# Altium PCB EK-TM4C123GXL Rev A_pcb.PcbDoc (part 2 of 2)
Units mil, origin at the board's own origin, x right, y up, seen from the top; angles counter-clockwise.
Board outline 2000 x 2600 mil, 2 copper layers (Top, Bottom), stack 12.7 mil thick; 107 components, 90 nets, 409 pads, 197 vias.
Unrouted connection lines stored in the file: 66.
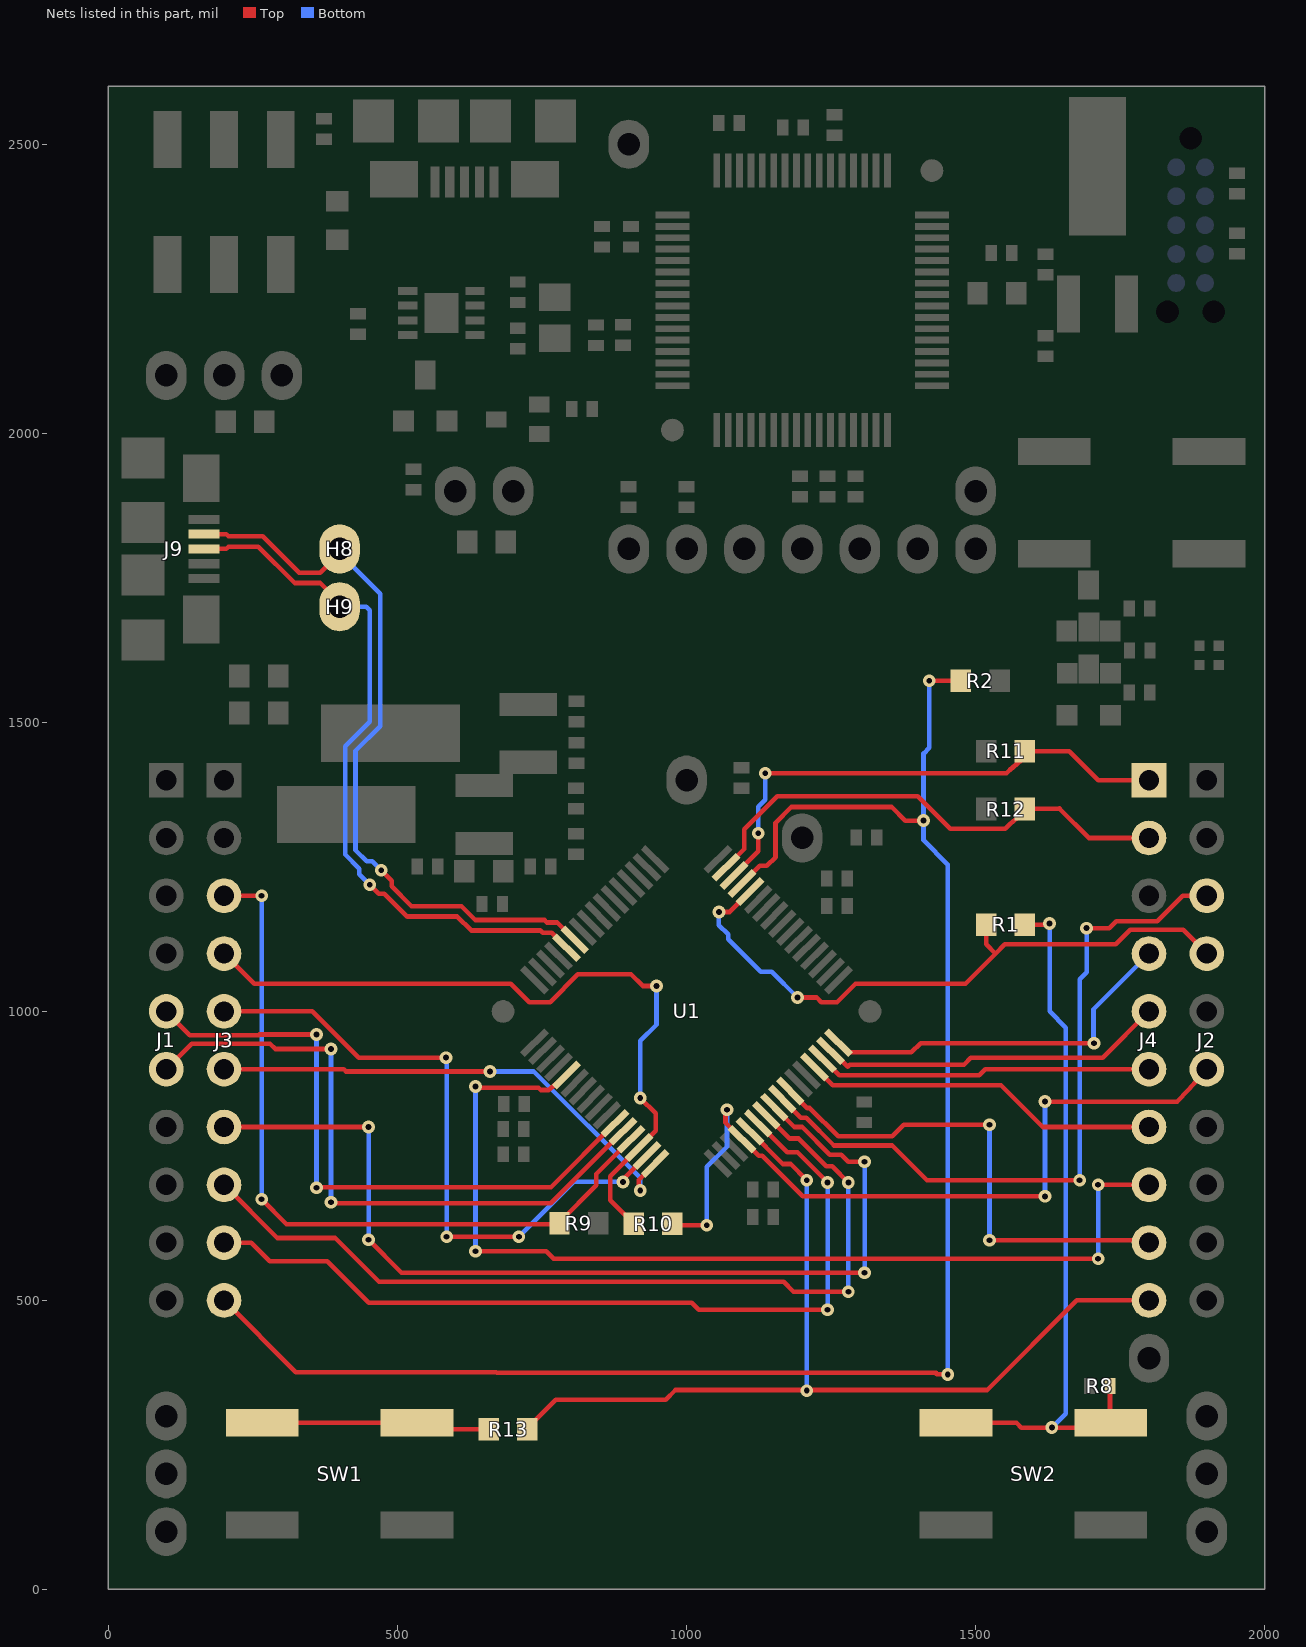
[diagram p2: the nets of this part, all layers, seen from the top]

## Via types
v1: diameter 22, hole 10, Top to Bottom, 197 vias

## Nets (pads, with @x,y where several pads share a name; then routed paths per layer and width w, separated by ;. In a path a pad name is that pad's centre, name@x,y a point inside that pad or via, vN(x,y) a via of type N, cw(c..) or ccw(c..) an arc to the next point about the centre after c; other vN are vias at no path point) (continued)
PB7: J2.6 R10.2 U1.4 | length 1376
  Top w8: R10.2@975.48,632.6 975.48,630 v1(1035,630) ; v1(1070,830) 1067.39,830 1067.39,807.34 U1.4@1096.04,778.68 1124.7,750.02 1131.1,750.02 1201.12,680 v1(1620,680) ; v1(1620,844) 1849,844 1868,864 J2.6@1900,900
  Bottom w8: v1(1035,630) 1035,731 1070,766 v1(1070,830) ; v1(1620,680) v1(1620,844)
PC4: J4.4 U1.16 | length 652.6
  Top w8: U1.16@1263.08,945.71 1279.78,929.01 1389.01,929.01 1405,945 v1(1705,945)
  Bottom w8: v1(1705,945) 1704,944 1704,1004 J4.4@1800,1100
PC5: J4.5 U1.15 | length 602.8
  Top w8: U1.15@1249.16,931.79 1250.51,933.14 1279.16,904.48 1282.68,908 1480,908 1492,920 1720,920 J4.5@1800,1000
PC6: J4.6 U1.14 | length 581.1
  Top w8: U1.14@1235.24,917.88 1263.9,889.22 1506.06,889.22 1516.84,900 J4.6@1800,900
PC7: J4.7 U1.13 | length 621.7
  Top w8: U1.13@1221.32,903.96 1253.27,872 1544,872 1616,800 J4.7@1800,800
PD0: J3.3 R9.1 U1.61 | length 1320.2
  Top w8: J3.3@200,1200 v1(265,1200) ; v1(265,675) 308,632 778.93,632 R9.1@780.27,633.34 780.27,635.31 844,699.04 844,718.73 U1.61@903.96,778.68
  Bottom w8: v1(265,675) v1(265,1200)
PD1: J3.4 R10.1 U1.62 | length 1294.9
  Top w8: J3.4@200,1100 252,1048 695.97,1048 727.97,1016 764,1016 812,1064 904,1064 924,1044 v1(948,1044) ; R10.1@908.55,632.6 907.49,632.6 907.49,633.51 868,673 868,714.89 U1.62@917.88,764.76 946.53,793.42 946.53,823.47 v1(920,850)
  Bottom w8: v1(920,850) 920,949.16 948,977.16 v1(948,1044)
PD2: J3.5 U1.63 | length 1140.5
  Top w8: J3.5@200,1000 352.89,1000 432.89,920 v1(584,920) ; v1(585,610) v1(710,610) ; v1(890,705) 891,705 892,704 892,711.05 U1.63@931.79,750.84
  Bottom w8: v1(584,920) 585,919 v1(585,610) ; v1@708,608 v1(710,610) 805,705 v1(890,705)
PD3: J3.6 U1.64 | length 883.9
  Top w8: J3.6@200,900 406.94,900 410.94,896 v1(660,896) ; v1(920,690) 920,688 917.06,690.94 917.06,708.27 U1.64@945.71,736.92
  Bottom w8: v1(660,896) 736,896 920,712 v1(920,690)
PD6: J4.8 U1.53 | length 1753.5
  Top w8: v1(635,585) 757,585 770,572 v1(1712,572) ; v1(635,870) 635,869 636,868 744,868 748,864 761.32,864 785.77,883.21 U1.53@792.6,890.04 ; v1(1712,700) J4.8@1800,700
  Bottom w8: v1(635,585) v1(635,870) ; v1(1712,572) v1(1712,700)
PD7: J4.9 U1.10 | length 865.1
  Top w8: U1.10@1179.56,862.2 1208.99,832.76 1213.48,832.76 1262.24,784 1356,784 1376,804 v1(1524,804) ; v1(1524,604) 1800,604 J4.9@1800,600
  Bottom w8: v1(1524,604) v1(1524,804)
PE0: J2.3 U1.9 | length 1244.6
  Top w8: U1.9@1165.64,848.28 1197.92,816 1207.05,816 1255.05,768 1356,768 1416,708 v1(1680,708) ; v1(1692,1144) 1731.55,1144 1743.55,1156 1814.49,1156 1858.49,1200 J2.3@1900,1200
  Bottom w8: v1(1680,708) 1680,1055.61 1692,1067.61 v1(1692,1144)
PE1: J3.7 U1.8 | length 1716.8
  Top w8: J3.7@200,800 v1(450,800) ; v1(450,605) 507,548 v1(1308,548) ; U1.8@1151.72,834.36 1186.08,800 1199.86,800 1247.86,752 1267.61,752 1279.61,740 v1(1308,740)
  Bottom w8: v1(450,605) 450,798 452,800 v1(450,800) ; v1(1308,548) v1(1308,740)
PE2: J3.8 U1.7 | length 1536.1
  Top w8: J3.8@200,700 292,608 392,608 468,532 1168,532 1185,515 v1(1280,515) ; U1.7@1137.8,820.44 1178.24,780 1193.93,780 1241.93,732 1252,732 v1(1280,704)
  Bottom w8: v1(1280,515) v1(1280,704)
PE3: J3.9 U1.6 | length 1474.6
  Top w8: J3.9@200,600 246.93,600 278.93,568 378.5,568 450.5,496 1008.88,496 1020.88,484 v1(1244,484) ; U1.6@1123.88,806.52 1174.4,756 1192,756 v1(1244,704)
  Bottom w8: v1(1244,484) v1(1244,704)
PE4: J1.5 U1.59 | length 1105.3
  Top w8: J1.5@100,1000 141,959 260,959 261,960 v1(360,960) ; v1(360,695) 360,696 765.6,696 U1.59@876.12,806.52
  Bottom w8: v1(360,695) v1(360,960)
PE5: J1.6 U1.60 | length 1132
  Top w8: J1.6@100,900 144,944 279.43,944 288.43,935 v1(385,935) ; v1(385,670) 384,669 384,668 765.44,668 U1.60@890.04,792.6
  Bottom w8: v1(385,670) v1(385,935)
PF0: J2.4 R1.1 U1.28 | length 1120.9
  Top w8: v1(1056,1172) 1074.56,1172 U1.28@1109.96,1207.4 ; v1(1192,1024) 1225.02,1024 1233.02,1016 1260.36,1016 1292.36,1048 1482.57,1048 1534.52,1099.96 ; R1.1@1518.54,1150 1518.54,1115.95 1534.52,1099.96 ; J2.4@1900,1100 1859,1141 1767.32,1141 1742.32,1116 1550.57,1116 1534.52,1099.96
  Bottom w8: v1(1056,1172) 1056,1149.14 1072,1133.14 1072,1124.89 1128.11,1068.78 1147.22,1068.78 v1(1192,1024)
PF1: J3.10 R2.1 U1.29 | length 2995.4
  Top w8: J3.10@200,500 324,376 671,376 672,375 1432,375 1433,372 v1(1452,372) ; U1.29@1096.04,1221.32 1126.71,1251.99 1139.1,1251.99 1154,1266.89 1154,1326.55 1180.95,1353.5 1354.73,1353.5 1378.23,1330 v1(1410,1330) ; v1(1420,1572) R2.1@1474.54,1572
  Bottom w8: v1(1420,1572) 1420,1456 1410,1446 v1(1410,1330) 1410,1296 1452,1254 v1(1452,372)
PF2: J4.1 R11.1 U1.30 | length 904.4
  Top w8: U1.30@1082.12,1235.24 1124,1277.11 v1(1124,1308) ; v1(1136,1412) 1553.46,1412 1558.99,1417.52 1585.46,1439.92 R11.1@1585.46,1450 1662,1450 1712,1400 J4.1@1800,1400
  Bottom w8: v1(1124,1308) 1124,1354 1136,1366 v1(1136,1412)
PF3: J4.2 R12.1 U1.31 | length 862.4
  Top w8: U1.31@1068.21,1249.16 1100,1280.95 1100,1315.11 1156.89,1372 1400,1372 1456,1316 1551.46,1316 1558.99,1323.52 1585.46,1345.92 R12.1@1585.46,1350 1645.14,1350.86 1696,1300 J4.2@1800,1300
PF4: J4.10 R13.1 U1.5 | length 1667.2
  Top w8: R13.1@724.75,277.06 724.75,279.02 773.73,328 964,328 981,345 v1@1207,345 ; U1.5@1109.96,792.6 1166.56,736 1180,736 v1(1208,708) ; v1(1208,344) v1@1207,345 ; J4.10@1800,500 1675,500 1520,345 v1@1207,345
  Bottom w8: v1(1208,344) v1(1208,708)
USB_DM: H8.1 J9.2 U1.43 | length 1300.5
  Top w8: J9.2@165.32,1825.59 204,1825.59 207.8,1821.8 266.93,1821.8 329.73,1759 366.5,1759 400,1792.5 H8.1@400,1800 ; v1(472,1244) 490.06,1225.94 490.06,1216.17 524.19,1182.04 610.79,1182.04 634.83,1158 754.23,1158 758.49,1153.74 776.66,1153.74 U1.43@806.52,1123.88
  Bottom w8: H8.1@400,1800 400,1792.5 469.99,1722.51 469.99,1493.49 427.39,1450.88 427.39,1278.84 446.67,1259.56 456.44,1259.56 v1(472,1244)
USB_DP: H9.1 J9.3 U1.44 | length 1234.2
  Top w8: J9.3@165.32,1800 204,1800 207.8,1803.8 259.48,1803.8 322.27,1741 366.5,1741 400,1707.5 H9.1@400,1700 ; v1(452,1219) 467.56,1203.44 477.33,1203.44 516.73,1164.04 603.34,1164.04 627.38,1140 746.86,1140 751.12,1135.74 766.82,1135.74 U1.44@792.6,1109.96
  Bottom w8: H9.1@400,1700 446,1700 451.99,1694.01 451.99,1500.94 409.39,1458.34 409.39,1271.38 433.94,1246.83 433.94,1237.06 v1(452,1219)
USR_SW1: R13.2 SW1.1 SW1.3 | length 403.2
  Top w8: SW1.1@266.14,288.58 SW1.3@533.86,288.58 533.86,277.06 R13.2@657.82,277.06
USR_SW2: R1.2 R8.2 SW2.1 SW2.3 | length 1300.2
  Top w8: SW2.1@1466.14,288.58 1570.78,288.58 1579.36,280 v1(1632,280) SW2.3@1732.51,280 ; R1.2@1585.46,1150 1626,1150 v1(1628,1152) ; R8.2@1732.51,352.28 SW2.3@1732.51,280 ; SW2.3@1732.51,280 SW2.3@1732.68,280 ; SW2.3@1732.51,280 1732.51,278.74 SW2.3@1732.68,280 ; SW2.3@1732.68,280 1733.86,280 SW2.3@1733.86,288.58 SW2.3@1732.68,280
  Bottom w8: v1(1628,1152) 1628,1000 1656,972 1656,304 v1(1632,280)
pads on no net: J5.1 J5.7 J5.11 J5.12 J5.13 J9.10 J9.11 J11.4 J11.10 J11.11 Q1.1 Q1.2 Q1.3 Q2.1 Q2.2 Q2.3 Q3.1 Q3.2 Q3.3 U1.65 U1.66 U2.1 U2.4 U2.5 U2.6 U2.7 U2.8 U2.9 U2.10 U2.13 U2.14 U2.15 U2.16 U2.28 U2.31 U2.33 U2.36 U2.47 U2.48 U2.57 U2.58 U2.59 U2.60 U2.61 U2.62 U2.63 U2.65 U2.66 U8.2 U8.6 U8.7 U8.10 U8.11 U8.12 U8.13 Y1.3 Y2.3 Y5.3
copper on no net: | length 550.8
  Bottom w4: 1734.32,1998.88 1734.5,1998.88 ; 1734.32,1999.6 1734.5,1999.6 ; 1734.32,2001.04 1736.66,2001.04 ; 1734.32,2001.76 1735.22,2001.76 ; 1735.04,2003.2 1735.22,2003.2 ; 1735.04,2003.92 1735.94,2003.92 ; 1735.76,2000.32 1735.94,2000.32 ; 1735.76,2002.48 1736.66,2002.48 ; 1735.76,2004.64 1737.38,2004.64 ; 1736.48,2001.76 1736.66,2001.76 ; 1736.48,2003.2 1738.1,2003.2 ; 1737.2,2005.36 1739.54,2005.36 ; 1737.92,2002.48 1738.1,2002.48 ; 1738.64,2003.92 1738.82,2003.92 ; 1738.64,2004.64 1738.82,2004.64 ; 1738.64,2006.08 1741.7,2006.08 ; 1739.36,2006.8 1742.42,2006.8 ; 1740.8,2007.52 1740.98,2007.52 ; 1740.8,2008.24 1743.86,2008.24 ; 1741.52,2008.96 1741.7,2008.96 ; 1741.52,2009.68 1742.42,2009.68 ; 1742.24,2007.52 1743.14,2007.52 ; 1742.24,2010.4 1743.14,2010.4 ; 1742.96,2011.12 1743.14,2011.12 ; 1742.96,2011.84 1744.58,2011.84 ; 1743.68,2008.96 1744.58,2008.96 ; 1743.68,2009.68 1745.3,2009.68 ; 1743.68,2012.56 1744.58,2012.56 ; 1744.4,1993.84 1745.3,1993.84 ; 1744.4,1994.56 1744.58,1994.56 ; 1744.4,1995.28 1745.3,1995.28 ; 1744.4,1996 1745.3,1996 ; 1744.4,1996.72 1745.3,1996.72 ; 1744.4,1997.44 1744.58,1997.44 ; 1744.4,1998.16 1745.3,1998.16 ; 1744.4,2010.4 1746.02,2010.4 ; 1744.4,2013.28 1746.02,2013.28 ; 1745.12,1991.68 1745.3,1991.68 ; 1745.12,1992.4 1745.3,1992.4 ; 1745.12,1993.12 1746.74,1993.12 ; 1745.12,1998.88 1745.3,1998.88 ; 1745.12,1999.6 1749.62,1999.6 ; 1745.12,2000.32 1746.74,2000.32 ; 1745.12,2001.04 1746.74,2001.04 ; 1745.12,2002.48 1746.74,2002.48 ; 1745.12,2011.12 1745.3,2011.12 ; 1745.84,1987.36 1746.74,1987.36 ; 1745.84,1988.08 1746.02,1988.08 ; 1745.84,1988.8 1746.02,1988.8 ; 1745.84,1989.52 1746.02,1989.52 ; 1745.84,1990.24 1746.02,1990.24 ; 1745.84,1990.96 1746.02,1990.96 ; 1745.84,2001.76 1746.74,2001.76 ; 1745.84,2003.92 1746.02,2003.92 ; 1745.84,2011.84 1746.02,2011.84 ; 1745.84,2014 1746.02,2014 ; 1745.84,2014.72 1746.74,2014.72 ; 1746.56,1985.92 1748.18,1985.92 ; 1746.56,1986.64 1746.74,1986.64 ; 1746.56,1993.84 1748.18,1993.84 ; 1746.56,2003.2 1747.46,2003.2 ; 1746.56,2004.64 1748.18,2004.64 ; 1746.56,2011.12 1746.74,2011.12 ; 1746.56,2015.44 1746.74,2015.44 ; 1746.56,2016.16 1748.18,2016.16 ; 1747.28,1983.04 1748.18,1983.04 ; 1747.28,1983.76 1747.46,1983.76 ; 1747.28,1984.48 1747.46,1984.48 ; 1747.28,1985.2 1748.9,1985.2 ; 1747.28,1998.88 1748.18,1998.88 ; 1747.28,2003.92 1748.18,2003.92 ; 1747.28,2005.36 1748.9,2005.36 ; 1747.28,2011.84 1747.46,2011.84 ; 1747.28,2012.56 1748.18,2012.56 ; 1747.28,2014 1747.46,2014 ; 1747.28,2016.88 1748.9,2016.88 ; 1748,1980.88 1748.9,1980.88 ; 1748,1981.6 1748.9,1981.6 ; 1748,1982.32 1748.18,1982.32 ; 1748,1986.64 1748.18,1986.64 ; 1748,1987.36 1748.18,1987.36 ; 1748,1988.08 1748.18,1988.08 ; 1748,1988.8 1748.18,1988.8 ; 1748,1989.52 1748.18,1989.52 ; 1748,1990.24 1748.18,1990.24 ; 1748,1990.96 1748.18,1990.96 ; 1748,1991.68 1748.18,1991.68 ; 1748,1992.4 1748.18,1992.4 ; 1748,1993.12 1748.18,1993.12 ; 1748,1994.56 1748.18,1994.56 ; 1748,1995.28 1748.18,1995.28 ; 1748,1996 1748.18,1996 ; 1748,1996.72 1748.18,1996.72 ; 1748,1997.44 1748.18,1997.44 ; 1748,1998.16 1748.18,1998.16 ; 1748,2000.32 1751.06,2000.32 ; 1748,2013.28 1748.9,2013.28 ; 1748.72,1980.16 1749.62,1980.16 ; 1748.72,1984.48 1749.62,1984.48 ; 1748.72,2006.08 1748.9,2006.08 ; 1748.72,2006.8 1749.62,2006.8 ; 1748.72,2014 1749.62,2014 ; 1748.72,2017.6 1751.06,2017.6 ; 1749.44,1979.44 1749.62,1979.44 ; 1749.44,1983.76 1750.34,1983.76 ; 1749.44,2001.04 1753.22,2001.04 ; 1749.44,2007.52 1749.62,2007.52 ; 1749.44,2014.72 1750.34,2014.72 ; 1749.44,2018.32 1749.62,2018.32 ; 1750.16,1978.72 1750.34,1978.72 ; 1750.16,2008.24 1750.34,2008.24 ; 1750.16,2008.96 1752.5,2008.96 ; 1750.88,1978 1751.06,1978 ; 1750.88,1983.04 1751.78,1983.04 ; 1750.88,2015.44 1752.5,2015.44 ; 1750.88,2018.32 1753.22,2018.32 ; 1751.6,1976.56 1752.5,1976.56 ; 1751.6,1977.28 1751.78,1977.28 ; 1751.6,1980.16 1752.5,1980.16 ; 1751.6,1980.88 1751.78,1980.88 ; 1751.6,1981.6 1751.78,1981.6 ; 1751.6,1982.32 1751.78,1982.32 ; 1751.6,2006.08 1753.22,2006.08 ; 1751.6,2006.8 1752.5,2006.8 ; 1751.6,2007.52 1752.5,2007.52 ; 1751.6,2008.24 1752.5,2008.24 ; 1752.32,1975.84 1753.22,1975.84 ; 1752.32,1978.72 1753.22,1978.72 ; 1752.32,1979.44 1752.5,1979.44 ; 1752.32,2001.76 1753.22,2001.76 ; 1752.32,2003.92 1753.22,2003.92 ; 1752.32,2004.64 1753.22,2004.64 ; 1752.32,2005.36 1753.22,2005.36 ; 1752.32,2009.68 1752.5,2009.68 ; 1752.32,2010.4 1752.5,2010.4 ; 1752.32,2011.12 1752.5,2011.12 ; 1752.32,2011.84 1752.5,2011.84 ; 1752.32,2012.56 1752.5,2012.56 ; 1752.32,2013.28 1752.5,2013.28 ; 1752.32,2014 1752.5,2014 ; 1752.32,2014.72 1752.5,2014.72 ; 1752.32,2016.16 1752.5,2016.16 ; 1752.32,2016.88 1752.5,2016.88 ; 1752.32,2017.6 1753.22,2017.6 ; 1752.32,2019.04 1753.94,2019.04 ; 1753.04,1975.12 1754.66,1975.12 ; 1753.04,1978 1754.66,1978 ; 1753.04,1997.44 1753.94,1997.44 ; 1753.04,1998.16 1753.94,1998.16 ; 1753.04,1998.88 1753.94,1998.88 ; 1753.04,1999.6 1753.94,1999.6 ; 1753.04,2000.32 1753.22,2000.32 ; 1753.04,2002.48 1753.22,2002.48 ; 1753.04,2003.2 1753.22,2003.2 ; 1753.04,2029.12 1753.22,2029.12 ; 1753.04,2029.84 1753.22,2029.84 ; 1753.04,2030.56 1753.22,2030.56 ; 1753.04,2031.28 1753.22,2031.28 ; 1753.76,1977.28 1754.66,1977.28 ; 1753.76,1996 1754.66,1996 ; 1753.76,1996.72 1753.94,1996.72 ; 1753.76,2019.76 1756.1,2019.76 ; 1753.76,2025.52 1756.1,2025.52 ; 1753.76,2026.24 1753.94,2026.24 ; 1753.76,2026.96 1753.94,2026.96 ; 1753.76,2027.68 1753.94,2027.68 ; 1753.76,2028.4 1753.94,2028.4 ; 1753.76,2032 1753.94,2032 ; 1753.76,2032.72 1753.94,2032.72 ; 1753.76,2033.44 1754.66,2033.44 ; 1754.48,1973.68 1754.66,1973.68 ; 1754.48,1974.4 1754.66,1974.4 ; 1754.48,1975.84 1754.66,1975.84 ; 1754.48,1976.56 1754.66,1976.56 ; 1754.48,1993.84 1754.66,1993.84 ; 1754.48,1994.56 1754.66,1994.56 ; 1754.48,1995.28 1754.66,1995.28 ; 1754.48,2024.08 1756.1,2024.08 ; 1754.48,2024.8 1754.66,2024.8 ; 1754.48,2029.12 1755.38,2029.12 ; 1754.48,2029.84 1755.38,2029.84 ; 1754.48,2034.16 1755.38,2034.16 ; 1755.2,1967.92 1755.38,1967.92 ; 1755.2,1968.64 1755.38,1968.64 ; 1755.2,1969.36 1757.54,1969.36 ; 1755.2,1970.08 1756.82,1970.08 ; 1755.2,1970.8 1756.1,1970.8 ; 1755.2,1972.24 1756.82,1972.24 ; 1755.2,1972.96 1756.1,1972.96 ; 1755.2,1991.68 1756.1,1991.68 ; 1755.2,1992.4 1755.38,1992.4 ; 1755.2,1993.12 1755.38,1993.12 ; 1755.2,2022.64 1756.82,2022.64 ; 1755.2,2023.36 1756.1,2023.36 ; 1755.2,2026.24 1755.38,2026.24 ; 1755.2,2026.96 1756.1,2026.96 ; 1755.2,2027.68 1755.38,2027.68 ; 1755.2,2028.4 1755.38,2028.4 ; 1755.2,2034.88 1756.1,2034.88 ; 1755.92,1966.48 1756.82,1966.48 ; 1755.92,1967.2 1756.82,1967.2 ; 1755.92,1971.52 1756.1,1971.52 ; 1755.92,1990.24 1756.82,1990.24 ; 1755.92,1990.96 1756.1,1990.96 ; 1755.92,2020.48 1757.54,2020.48 ; 1755.92,2021.92 1763.3,2021.92 ; 1755.92,2024.8 1756.1,2024.8 ; 1755.92,2030.56 1756.82,2030.56 ; 1755.92,2035.6 1756.1,2035.6 ; 1756.64,1964.32 1758.26,1964.32 ; 1756.64,1965.76 1757.54,1965.76 ; 1756.64,1989.52 1757.54,1989.52 ; 1756.64,2021.2 1758.26,2021.2 ; 1756.64,2031.28 1756.82,2031.28 ; 1756.64,2032 1757.54,2032 ; 1756.64,2036.32 1758.26,2036.32 ; 1757.36,1963.6 1761.86,1963.6 ; 1757.36,1965.04 1757.54,1965.04 ; 1757.36,1968.64 1758.26,1968.64 ; 1757.36,1988.8 1758.26,1988.8 ; 1757.36,2032.72 1757.54,2032.72 ; 1757.36,2033.44 1758.26,2033.44 ; 1757.36,2039.92 1758.26,2039.92 ; 1757.36,2040.64 1758.26,2040.64 ; 1757.36,2041.36 1758.26,2041.36 ; 1757.36,2042.08 1758.98,2042.08 ; 1757.36,2042.8 1759.7,2042.8 ; 1757.36,2043.52 1757.54,2043.52 ; 1757.36,2044.24 1758.26,2044.24 ; 1757.36,2044.96 1758.26,2044.96 ; 1758.08,1962.88 1758.98,1962.88 ; 1758.08,1987.36 1758.98,1987.36 ; 1758.08,1988.08 1758.26,1988.08 ; 1758.08,2034.16 1758.98,2034.16 ; 1758.08,2034.88 1759.7,2034.88 ; 1758.08,2035.6 1758.26,2035.6 ; 1758.08,2037.04 1758.26,2037.04 ; 1758.08,2037.76 1758.26,2037.76 ; 1758.08,2038.48 1758.98,2038.48 ; 1758.08,2039.2 1758.98,2039.2 ; 1758.08,2045.68 1758.98,2045.68 ; 1758.8,1985.92 1759.7,1985.92 ; 1758.8,1986.64 1758.98,1986.64 ; 1758.8,2022.64 1760.42,2022.64 ; 1758.8,2043.52 1758.98,2043.52 ; 1758.8,2046.4 1760.42,2046.4 ; 1759.52,1961.44 1764.02,1961.44 ; 1759.52,1962.16 1760.42,1962.16 ; 1759.52,1984.48 1760.42,1984.48 ; 1759.52,1985.2 1759.7,1985.2 ; 1759.52,2035.6 1761.14,2035.6 ; 1759.52,2044.24 1759.7,2044.24 ; 1760.24,1983.76 1761.86,1983.76 ; 1760.24,2044.96 1760.42,2044.96 ; 1760.24,2047.12 1760.42,2047.12 ; 1761.68,1964.32 1762.58,1964.32 ; 1761.68,1982.32 1761.86,1982.32 ; 1761.68,1983.04 1762.58,1983.04 ; 1761.68,2021.2 1763.3,2021.2 ; 1761.68,2036.32 1766.18,2036.32 ; 1762.4,1981.6 1764.02,1981.6 ; 1762.4,2037.04 1763.3,2037.04 ; 1762.4,2037.76 1764.02,2037.76 ; 1763.12,1962.16 1764.74,1962.16 ; 1763.12,1962.88 1764.02,1962.88 ; 1763.12,1963.6 1763.3,1963.6 ; 1763.12,1980.88 1764.74,1980.88 ; 1763.12,1982.32 1763.3,1982.32 ; 1763.84,2020.48 1769.78,2020.48 ; 1763.84,2038.48 1764.02,2038.48 ; 1763.84,2039.2 1764.74,2039.2 ; 1763.84,2039.92 1764.74,2039.92 ; 1763.84,2040.64 1764.74,2040.64 ; 1763.84,2041.36 1765.46,2041.36 ; 1763.84,2042.08 1765.46,2042.08 ; 1764.56,1980.16 1765.46,1980.16 ; 1764.56,2021.2 1765.46,2021.2 ; 1764.56,2042.8 1773.38,2042.8 ; 1765.28,1979.44 1766.9,1979.44 ; 1766,2019.76 1768.34,2019.76 ; 1766,2037.04 1771.22,2037.04 ; 1766,2043.52 1772.66,2043.52 ; 1766.72,1978.72 1769.78,1978.72 ; 1767.44,2019.04 1768.34,2019.04 ; 1768.16,1978 1769.06,1978 ; 1768.16,1979.44 1769.78,1979.44 ; 1768.16,2018.32 1769.06,2018.32 ; 1768.88,1980.16 1770.5,1980.16 ; 1768.88,2017.6 1770.5,2017.6 ; 1769.6,2014.72 1770.5,2014.72 ; 1769.6,2015.44 1770.5,2015.44 ; 1769.6,2016.16 1770.5,2016.16 ; 1769.6,2016.88 1770.5,2016.88 ; 1769.6,2042.08 1774.1,2042.08 ; 1770.32,1980.88 1771.94,1980.88 ; 1770.32,1993.84 1771.22,1993.84 ; 1770.32,1994.56 1771.22,1994.56 ; 1770.32,1995.28 1771.22,1995.28 ; 1770.32,1996 1771.22,1996 ; 1770.32,1996.72 1770.5,1996.72 ; 1770.32,1997.44 1770.5,1997.44 ; 1770.32,1998.16 1770.5,1998.16 ; 1770.32,1998.88 1770.5,1998.88 ; 1770.32,1999.6 1770.5,1999.6 ; 1770.32,2000.32 1770.5,2000.32 ; 1770.32,2001.04 1770.5,2001.04 ; 1770.32,2001.76 1770.5,2001.76 ; 1770.32,2002.48 1770.5,2002.48 ; 1770.32,2003.2 1770.5,2003.2 ; 1770.32,2003.92 1770.5,2003.92 ; 1770.32,2004.64 1770.5,2004.64 ; 1770.32,2005.36 1770.5,2005.36 ; 1770.32,2006.08 1770.5,2006.08 ; 1770.32,2006.8 1770.5,2006.8 ; 1770.32,2007.52 1771.22,2007.52 ; 1770.32,2008.24 1771.22,2008.24 ; 1770.32,2008.96 1771.22,2008.96 ; 1770.32,2009.68 1770.5,2009.68 ; 1770.32,2010.4 1770.5,2010.4 ; 1770.32,2011.12 1770.5,2011.12 ; 1770.32,2011.84 1770.5,2011.84 ; 1770.32,2012.56 1770.5,2012.56 ; 1770.32,2013.28 1770.5,2013.28 ; 1770.32,2014 1770.5,2014 ; 1771.04,1981.6 1771.94,1981.6 ; 1771.04,1990.24 1771.94,1990.24 ; 1771.04,1990.96 1771.94,1990.96 ; 1771.04,1993.12 1771.94,1993.12 ; 1771.04,2018.32 1771.22,2018.32 ; 1771.04,2019.04 1771.94,2019.04 ; 1771.04,2019.76 1774.82,2019.76 ; 1771.04,2020.48 1772.66,2020.48 ; 1771.04,2036.32 1777.7,2036.32 ; 1771.76,1979.44 1772.66,1979.44 ; 1771.76,1980.16 1771.94,1980.16 ; 1771.76,1982.32 1771.94,1982.32 ; 1771.76,1983.04 1772.66,1983.04 ; 1771.76,1983.76 1772.66,1983.76 ; 1771.76,1988.08 1772.66,1988.08 ; 1771.76,1988.8 1771.94,1988.8 ; 1771.76,1989.52 1771.94,1989.52 ; 1771.76,1991.68 1771.94,1991.68 ; 1771.76,1992.4 1771.94,1992.4 ; 1772.48,1978.72 1777.7,1978.72 ; 1772.48,1984.48 1772.66,1984.48 ; 1772.48,1985.2 1772.66,1985.2 ; 1772.48,1985.92 1772.66,1985.92 ; 1772.48,1986.64 1772.66,1986.64 ; 1772.48,1987.36 1772.66,1987.36 ; 1773.2,2039.2 1774.1,2039.2 ; 1773.2,2040.64 1774.1,2040.64 ; 1773.2,2041.36 1774.1,2041.36 ; 1773.92,2037.76 1775.54,2037.76 ; 1773.92,2038.48 1774.82,2038.48 ; 1773.92,2039.92 1774.1,2039.92 ; 1774.64,1978 1776.26,1978 ; 1774.64,2020.48 1775.54,2020.48 ; 1774.64,2037.04 1774.82,2037.04 ; 1775.36,2021.2 1777.7,2021.2 ; 1776.8,2035.6 1779.86,2035.6 ; 1777.52,1979.44 1778.42,1979.44 ; 1777.52,2021.92 1779.86,2021.92 ; 1778.24,1980.16 1779.14,1980.16 ; 1778.96,1962.16 1779.86,1962.16 ; 1778.96,1962.88 1782.74,1962.88 ; 1778.96,1963.6 1779.14,1963.6 ; 1778.96,1964.32 1779.14,1964.32 ; 1778.96,1965.04 1779.14,1965.04 ; 1778.96,1980.88 1779.86,1980.88 ; 1779.68,1961.44 1780.58,1961.44 ; 1779.68,1965.76 1780.58,1965.76 ; 1779.68,1966.48 1782.02,1966.48 ; 1779.68,1981.6 1781.3,1981.6 ; 1779.68,2034.88 1782.02,2034.88 ; 1780.4,1960.72 1784.18,1960.72 ; 1780.4,1982.32 1782.02,1982.32 ; 1780.4,2022.64 1782.74,2022.64 ; 1780.4,2034.16 1781.3,2034.16 ; 1780.4,2043.52 1780.58,2043.52 ; 1780.4,2044.96 1781.3,2044.96 ; 1780.4,2047.84 1780.58,2047.84 ; 1781.12,1967.2 1782.74,1967.2 ; 1781.12,1969.36 1783.46,1969.36 ; 1781.12,1970.08 1782.02,1970.08 ; 1781.12,1983.04 1783.46,1983.04 ; 1781.12,2033.44 1782.74,2033.44 ; 1781.12,2044.24 1782.02,2044.24 ; 1781.12,2045.68 1782.02,2045.68 ; 1781.12,2046.4 1781.3,2046.4 ; 1781.12,2047.12 1781.3,2047.12 ; 1781.84,1963.6 1782.74,1963.6 ; 1781.84,1964.32 1782.74,1964.32 ; 1781.84,1965.04 1782.74,1965.04 ; 1781.84,1965.76 1782.02,1965.76 ; 1781.84,1967.92 1782.74,1967.92 ; 1781.84,1968.64 1782.74,1968.64 ; 1781.84,1970.8 1784.18,1970.8 ; 1781.84,1971.52 1782.02,1971.52 ; 1781.84,1972.24 1782.74,1972.24 ; 1781.84,1972.96 1782.74,1972.96 ; 1781.84,1983.76 1782.74,1983.76 ; 1781.84,2032.72 1782.74,2032.72 ; 1781.84,2035.6 1782.02,2035.6 ; 1781.84,2036.32 1783.46,2036.32 ; 1781.84,2042.8 1782.74,2042.8 ; 1781.84,2043.52 1782.02,2043.52 ; 1782.56,1961.44 1784.18,1961.44 ; 1782.56,1962.16 1783.46,1962.16 ; 1782.56,1973.68 1782.74,1973.68 ; 1782.56,1974.4 1783.46,1974.4 ; 1782.56,1984.48 1784.9,1984.48 ; 1782.56,2021.92 1784.9,2021.92 ; 1782.56,2032 1783.46,2032 ; 1782.56,2037.04 1782.74,2037.04 ; 1782.56,2037.76 1782.74,2037.76 ; 1782.56,2038.48 1782.74,2038.48 ; 1782.56,2039.2 1782.74,2039.2 ; 1782.56,2039.92 1782.74,2039.92 ; 1782.56,2040.64 1782.74,2040.64 ; 1782.56,2041.36 1782.74,2041.36 ; 1782.56,2042.08 1782.74,2042.08 ; 1783.28,1970.08 1783.46,1970.08 ; 1783.28,1975.12 1784.18,1975.12 ; 1783.28,1975.84 1784.18,1975.84 ; 1783.28,2028.4 1784.18,2028.4 ; 1783.28,2029.12 1783.46,2029.12 ; 1783.28,2029.84 1783.46,2029.84 ; 1783.28,2030.56 1783.46,2030.56 ; 1783.28,2031.28 1783.46,2031.28 ; 1783.28,2034.16 1784.18,2034.16 ; 1783.28,2034.88 1783.46,2034.88 ; 1783.28,2035.6 1783.46,2035.6 ; 1784,1960 1784.18,1960 ; 1784,1971.52 1784.9,1971.52 ; 1784,1976.56 1784.9,1976.56 ; 1784,1983.76 1784.18,1983.76 ; 1784,1985.2 1785.62,1985.2 ; 1784,2024.08 1785.62,2024.08 ; 1784,2024.8 1784.9,2024.8 ; 1784,2025.52 1784.18,2025.52 ; 1784,2026.24 1784.18,2026.24 ; 1784,2026.96 1784.18,2026.96 ; 1784,2027.68 1784.18,2027.68 ; 1784,2032.72 1784.9,2032.72 ; 1784,2033.44 1784.9,2033.44 ; 1784.72,1972.24 1784.9,1972.24 ; 1784.72,1972.96 1785.62,1972.96 ; 1784.72,1977.28 1785.62,1977.28 ; 1784.72,2021.2 1786.34,2021.2 ; 1784.72,2022.64 1785.62,2022.64 ; 1784.72,2023.36 1784.9,2023.36 ; 1784.72,2031.28 1785.62,2031.28 ; 1784.72,2032 1785.62,2032 ; 1785.44,1973.68 1785.62,1973.68 ; 1785.44,1974.4 1786.34,1974.4 ; 1785.44,1978 1785.62,1978 ; 1785.44,1978.72 1785.62,1978.72 ; 1785.44,1985.92 1786.34,1985.92 ; 1785.44,2029.84 1786.34,2029.84 ; 1785.44,2030.56 1786.34,2030.56 ; 1786.16,1975.12 1787.06,1975.12 ; 1786.16,1979.44 1786.34,1979.44 ; 1786.16,1980.16 1787.78,1980.16 ; 1786.16,1986.64 1787.06,1986.64 ; 1786.16,2020.48 1788.5,2020.48 ; 1786.16,2024.8 1786.34,2024.8 ; 1786.16,2025.52 1786.34,2025.52 ; 1786.16,2026.24 1786.34,2026.24 ; 1786.16,2026.96 1786.34,2026.96 ; 1786.16,2027.68 1786.34,2027.68 ; 1786.16,2028.4 1786.34,2028.4 ; 1786.16,2029.12 1786.34,2029.12 ; 1786.88,1975.84 1787.78,1975.84 ; 1786.88,1976.56 1787.78,1976.56 ; 1786.88,1980.88 1787.78,1980.88 ; 1786.88,1987.36 1787.06,1987.36 ; 1786.88,1988.08 1787.06,1988.08 ; 1786.88,1988.8 1787.06,1988.8 ; 1786.88,1989.52 1787.06,1989.52 ; 1786.88,1990.24 1787.78,1990.24 ; 1786.88,1990.96 1787.78,1990.96 ; 1787.6,1977.28 1788.5,1977.28 ; 1787.6,1981.6 1788.5,1981.6 ; 1787.6,1991.68 1787.78,1991.68 ; 1787.6,1992.4 1788.5,1992.4 ; 1787.6,1993.12 1788.5,1993.12 ; 1788.32,1978 1789.22,1978 ; 1788.32,1982.32 1789.22,1982.32 ; 1788.32,1993.84 1788.5,1993.84 ; 1788.32,1994.56 1788.5,1994.56 ; 1788.32,1995.28 1788.5,1995.28 ; 1788.32,1996 1789.22,1996 ; 1788.32,1996.72 1789.22,1996.72 ; 1788.32,2017.6 1789.22,2017.6 ; 1788.32,2018.32 1788.5,2018.32 ; 1788.32,2019.04 1790.66,2019.04 ; 1788.32,2019.76 1789.22,2019.76 ; 1789.04,1979.44 1790.66,1979.44 ; 1789.04,1983.04 1790.66,1983.04 ; 1789.04,1997.44 1789.22,1997.44 ; 1789.04,1998.16 1789.22,1998.16 ; 1789.04,1998.88 1789.22,1998.88 ; 1789.04,1999.6 1789.22,1999.6 ; 1789.04,2000.32 1789.94,2000.32 ; 1789.04,2001.04 1791.38,2001.04 ; 1789.04,2001.76 1791.38,2001.76 ; 1789.04,2016.88 1789.94,2016.88 ; 1789.76,1978.72 1789.94,1978.72 ; 1789.76,1980.16 1790.66,1980.16 ; 1789.76,2002.48 1789.94,2002.48 ; 1789.76,2003.2 1789.94,2003.2 ; 1789.76,2003.92 1789.94,2003.92 ; 1789.76,2004.64 1789.94,2004.64 ; 1789.76,2005.36 1789.94,2005.36 ; 1789.76,2006.08 1789.94,2006.08 ; 1789.76,2006.8 1789.94,2006.8 ; 1789.76,2007.52 1791.38,2007.52 ; 1789.76,2008.24 1789.94,2008.24 ; 1789.76,2008.96 1789.94,2008.96 ; 1789.76,2009.68 1789.94,2009.68 ; 1789.76,2010.4 1789.94,2010.4 ; 1789.76,2011.12 1789.94,2011.12 ; 1789.76,2011.84 1789.94,2011.84 ; 1789.76,2012.56 1789.94,2012.56 ; 1789.76,2013.28 1789.94,2013.28 ; 1789.76,2014 1789.94,2014 ; 1789.76,2014.72 1789.94,2014.72 ; 1789.76,2015.44 1795.7,2015.44 ; 1789.76,2016.16 1791.38,2016.16 ; 1789.76,2018.32 1791.38,2018.32 ; 1790.48,1980.88 1791.38,1980.88 ; 1790.48,1983.76 1791.38,1983.76 ; 1790.48,1984.48 1793.54,1984.48 ; 1790.48,2017.6 1792.1,2017.6 ; 1791.2,1981.6 1792.1,1981.6 ; 1791.2,1982.32 1792.1,1982.32 ; 1791.2,1999.6 1792.1,1999.6 ; 1791.2,2000.32 1791.38,2000.32 ; 1791.2,2002.48 1792.82,2002.48 ; 1791.2,2006.8 1792.1,2006.8 ; 1791.92,1983.04 1792.82,1983.04 ; 1791.92,1985.2 1792.1,1985.2 ; 1791.92,1985.92 1794.26,1985.92 ; 1791.92,1986.64 1792.1,1986.64 ; 1791.92,1987.36 1792.1,1987.36 ; 1791.92,1988.08 1792.1,1988.08 ; 1791.92,1988.8 1792.1,1988.8 ; 1791.92,1989.52 1792.1,1989.52 ; 1791.92,1990.24 1792.1,1990.24 ; 1791.92,1990.96 1792.1,1990.96 ; 1791.92,1991.68 1792.82,1991.68 ; 1791.92,1992.4 1792.82,1992.4 ; 1791.92,1993.12 1793.54,1993.12 ; 1791.92,1993.84 1794.98,1993.84 ; 1791.92,1997.44 1792.82,1997.44 ; 1791.92,1998.16 1792.1,1998.16 ; 1791.92,1998.88 1792.1,1998.88 ; 1791.92,2003.2 1794.98,2003.2 ; 1791.92,2006.08 1792.82,2006.08 ; 1791.92,2016.88 1793.54,2016.88 ; 1792.64,1983.76 1792.82,1983.76 ; 1792.64,1994.56 1793.54,1994.56 ; 1792.64,1995.28 1792.82,1995.28 ; 1792.64,1996 1792.82,1996 ; 1792.64,1996.72 1792.82,1996.72 ; 1792.64,2005.36 1792.82,2005.36 ; 1792.64,2014.72 1793.54,2014.72 ; 1793.36,1985.2 1793.54,1985.2 ; 1793.36,1986.64 1794.26,1986.64 ; 1793.36,2003.92 1794.26,2003.92 ; 1793.36,2004.64 1793.54,2004.64 ; 1793.36,2013.28 1794.26,2013.28 ; 1793.36,2014 1793.54,2014 ; 1793.36,2016.16 1794.98,2016.16 ; 1794.08,1987.36 1794.98,1987.36 ; 1794.08,2001.04 1794.98,2001.04 ; 1794.08,2001.76 1794.26,2001.76 ; 1794.08,2002.48 1794.98,2002.48 ; 1794.08,2012.56 1794.98,2012.56 ; 1794.8,1988.08 1794.98,1988.08 ; 1794.8,1988.8 1794.98,1988.8 ; 1794.8,1989.52 1794.98,1989.52 ; 1794.8,1990.24 1794.98,1990.24 ; 1794.8,1990.96 1794.98,1990.96 ; 1794.8,1991.68 1794.98,1991.68 ; 1794.8,1992.4 1794.98,1992.4 ; 1794.8,1993.12 1794.98,1993.12 ; 1794.8,1994.56 1794.98,1994.56 ; 1794.8,1995.28 1794.98,1995.28 ; 1794.8,1996 1794.98,1996 ; 1794.8,1996.72 1794.98,1996.72 ; 1794.8,1997.44 1794.98,1997.44 ; 1794.8,1998.16 1794.98,1998.16 ; 1794.8,1998.88 1794.98,1998.88 ; 1794.8,1999.6 1794.98,1999.6 ; 1794.8,2000.32 1794.98,2000.32 ; 1794.8,2014.72 1796.42,2014.72 ; 1795.52,2010.4 1797.86,2010.4 ; 1795.52,2011.12 1796.42,2011.12 ; 1795.52,2011.84 1795.7,2011.84 ; 1795.52,2014 1797.14,2014 ; 1796.24,2013.28 1797.86,2013.28 ; 1796.96,2008.96 1797.86,2008.96 ; 1796.96,2009.68 1798.58,2009.68 ; 1796.96,2012.56 1797.86,2012.56 ; 1797.68,2011.12 1799.3,2011.12 ; 1797.68,2011.84 1798.58,2011.84 ; 1798.4,2007.52 1799.3,2007.52 ; 1798.4,2008.24 1798.58,2008.24 ; 1799.12,2006.8 1801.46,2006.8 ; 1799.12,2008.96 1800.02,2008.96 ; 1799.12,2010.4 1799.3,2010.4 ; 1799.84,2008.24 1800.74,2008.24 ; 1799.84,2009.68 1800.02,2009.68 ; 1800.56,2006.08 1801.46,2006.08 ; 1800.56,2007.52 1800.74,2007.52 ; 1801.28,2005.36 1802.18,2005.36 ; 1802,2004.64 1803.62,2004.64 ; 1802.72,2003.92 1803.62,2003.92 ; 1802.72,2006.08 1802.9,2006.08 ; 1803.44,2005.36 1803.62,2005.36 ; 1804.16,2002.48 1805.78,2002.48 ; 1804.16,2003.2 1805.78,2003.2 ; 1804.88,2001.76 1805.78,2001.76 ; 1804.88,2003.92 1805.06,2003.92 ; 1805.6,1999.6 1805.78,1999.6 ; 1805.6,2000.32 1805.78,2000.32 ; 1805.6,2001.04 1805.78,2001.04

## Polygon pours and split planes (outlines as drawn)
GND on Top "Top-GND" (solid, remove dead copper, pour order 0): 20,2580 1980,2580 1980,20 20,20
GND on Bottom "Bottom-GND" (solid, remove dead copper, pour order 2): 20,2580 1980,2580 1980,20 20,20

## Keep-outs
Keep-Out Layer:
  the board outline again, w10

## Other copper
Top:
  pour cut-out: 24,1940 252,1940 276,1916 276,1680 248,1652 24,1652 24,1940
  pour cut-out: 600,1560 840,1560 840,1420 820,1400 820,1280 600,1280 600,1560
  pour cut-out: 1644,2340 1660,2356 1760,2356 1776,2340 1776,2100 1764,2088 1660,2088 1644,2104 1644,2340
  pour cut-out: 468,2588 764,2588 764,2344 744,2324 488,2324 468,2344 468,2588
  pour cut-out: 596,1560 412,1560 384,1532 384,1416 416,1384 500,1384 500,1288 512,1276 596,1276 596,1560
  pour cut-out: 1256,1972 1320,1972 1320,1916 1256,1916 1256,1972
Bottom:
  pour cut-out: 1724,2028 1756,2060 1788,2060 1820,2028 1820,1972 1792,1944 1752,1944 1724,1972 1724,2028
  pour cut-out: 1998,96 1920,96 1920,0 1998,0 1998,96
  pour cut-out: 1824,2480 1920,2480 1920,2240 1824,2240 1824,2480

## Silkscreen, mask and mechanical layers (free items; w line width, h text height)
Silkscreen Top:
  drawing of 4304 lines, arcs and shapes, not listed
  text "PWR SELECT" at 76,2564 h25
  text "DEBUG" at 792,2388 h25
  text "PWR" at 816,2244 h25
  text "DEVICE" at 28,2200 h25
  text "DEBUG" at 240,2200 h25
  text "RESET" at 1440,1956 h25
  text "VDD" at 616.41,1950 h25
  text "TCK" at 866.41,1700 h25
  text "TMS" at 965.76,1700 h25
  text "TDO" at 1066.53,1700 h25
  text "TDI" at 1176.05,1700 h25
  text "EXT" at 1267.72,1700 h25
  text "TXD" at 1367.72,1700 h25
  text "RXD" at 1466.41,1700 h25
  text "DBG" at 1265.82,1650 h25
  text "www.ti.com/launchpad" at 750.13,1583.11 h37.5
  text "DEVICE" at 48,1548 h25
  text "EK-TM4C123GXL  REV A" at 928,1480 h35
  text "+3.3V VBUS" at 250,1384.5 h25
  text "PF2 GND" at 1597.72,1384.5 h25
  text "VDDC" at 1152,1360 h25
  text "PB5 GND" at 250,1284.5 h25
  text "PF3 PB2" at 1600.34,1284.5 h25
  text "PB0 PD0" at 250,1184.5 h25
  text "PB3 P30" at 1596.41,1184.5 h25
  text "PB1 PD1" at 250,1084.5 h25
  text "PC4 PF0" at 1597.72,1084.5 h25
  text "PE4 PD2" at 250,984.5 h25
  text "PC5 RST" at 1593.79,984.5 h25
  text "PE5 PD3" at 250,884.5 h25
  text "PC6 PB7" at 1595.1,884.5 h25
  text "PB4 PE1" at 250,784.5 h25
  text "PC7 PB6" at 1594.98,784.5 h25
  text "PA5 PE2" at 250,684.5 h25
  text "PD6 PA4" at 1593.91,684.5 h25
  text "PA6 PE3" at 250,584.5 h25
  text "PD7 PA3" at 1593.79,584.5 h25
  text "PA7 PF1" at 250,484.5 h25
  text "PF4 PA2" at 1597.72,484.5 h25
  text "WAKE" at 1848,384 h25
  text "+VBUS" at 20,15 h25
  text "+3.3V" at 1840,15 h25
Silkscreen Bottom:
  text "VBUS  +3.3V" at 544,1384.5 h25
  text "GND   PF2" at 1701.56,1384.5 h25
  text "GND   PB5" at 544,1284.5 h25
  text "PB2   PF3" at 1698.94,1284.5 h25
  text "PD0   PB0" at 544,1184.5 h25
  text "PE0   PB3" at 1700.25,1184.5 h25
  text "PD1   PB1" at 544,1084.5 h25
  text "PF0   PC4" at 1702.75,1084.5 h25
  text "PD2   PE4" at 544,984.5 h25
  text "RST   PC5" at 1702.86,984.5 h25
  text "PD3   PE5" at 544,884.5 h25
  text "PB7   PC6" at 1704.29,884.5 h25
  text "PE1   PB4" at 544,784.5 h25
  text "PB6   PC7" at 1704.17,784.5 h25
  text "PE2   PA5" at 544,684.5 h25
  text "PA4   PD6" at 1704.29,684.5 h25
  text "PE3   PA6" at 544,584.5 h25
  text "PA3   PD7" at 1705.48,584.5 h25
  text "PF1   PA7" at 544,484.5 h25
  text "PA2   PF4" at 1702.75,484.5 h25
Assembly Drawing Top:
  lines w3: 516,2144 516,2272 636,2272 636,2144 516,2144 ; 556,1852 556,1952 752,1952 752,1852 556,1852
Layer_16:
  lines w10: 3015,2858 3015,5818 7216,5818 7216,2858 3015,2858
Drill Drawing:
  lines w10: 3126,5577 5476,5577 ; 83.05,4281.4 1433.05,4281.4 1383.05,4331.4 1458.05,4406.4 1408.05,4456.4 83.05,4456.4 83.05,4281.4 ; 83.05,4481.4 1433.05,4481.4 1383.05,4531.4 1458.05,4606.4 1408.05,4656.4 83.05,4656.4 83.05,4481.4 ; 83.05,4681.4 1433.05,4681.4 1383.05,4731.4 1458.05,4806.4 1408.05,4856.4 83.05,4856.4 83.05,4681.4 ; 89.05,3877.4 1439.05,3877.4 1389.05,3927.4 1464.05,4002.4 1414.05,4052.4 89.05,4052.4 89.05,3877.4 ; 89.05,4079.9 1439.05,4079.9 1389.05,4129.9 1464.05,4204.9 1414.05,4254.9 89.05,4254.9 89.05,4079.9
  text "NOTES :" at 3156,5637 h75
  text "UNLESS OTHERWISE SPECIFIED" at 3816,5637 h50
  text "1. MANUFACTURE IN ACCORDANCE WITH IPC-6012, TYPE 3, CLASS 2." at 3126,5452 h50
  text "2. END PRODUCT FEATURES SHALL NOT VARY MORE THAN 20% FROM" at 3126,5327 h50
  text "ARTWORK ORIGINALS." at 3251,5202 h50
  text "3. MATERIAL SHALL BE ROHS COMPLIANT, COPPER CLAD FR-406, NEMA GRADE (Tg 170degC)" at 3126,5077 h50
  text "PER IPC-4101, COLOR NATURAL." at 3251,4952 h50
  text "FILE NAMES" at 1683.05,4929.4 h75
  text "LAYER STACKUP" at 249.05,4920.4 h75
  text "4. CONSTRUCTION SHALL BE SYMMETRICAL MULTILAYER PER LAYER STACKUP DETAIL." at 3126,4827 h50
  text "EK-LM4F120XL_SST.PHO" at 1698.05,4731.4 h50
  text "TOP SILKSCREEN" at 233.05,4729.4 h60
  text "5. COPPER WEIGHT ON INNER LAYERS SHALL BE 1 OZ./SQ. FT.." at 3121,4702 h50
  text "6. EQUIVALENT COPPER WEIGHT ON OUTER LAYERS SHALL BE" at 3116,4572 h50
  text "EK-LM4F120XL_SMT.PHO" at 1698.05,4531.4 h50
  text "TOP SOLDER MASK" at 233.05,4529.4 h60
  text "1.0 OZ./SQ. FT BEFORE PLATING." at 3241,4447 h50
  text "EK-LM4F120XL_Top.PHO" at 1698.05,4331.4 h50
  text "COMPONENT SIDE" at 233.05,4329.4 h60
  text "7. ALL PLATED THROUGH HOLES SHALL HAVE A MINIMUM OF 0.0007\" COPPER." at 3116,4322 h50
  text "8. DRILL HOLE TOLERANCE AFTER PLATING SHALL BE +/- .003\"." at 3116,4197 h50
  text "SOLDER SIDE" at 239.05,4125.4 h60
  text "EK-LM4F120XL_BOT.PHO" at 1709.05,4125.4 h50
  text "9. MINIMUM ANNULAR RING SHALL BE 0.001\"." at 3116,4072 h50
  text "10. MINIMUM ANNULAR RING AT EMERGENT CONDUCTORS SHALL BE 0.003\"." at 3116,3947 h50
  text "BOTTOM SOLDER MASK" at 182.53,3926.41 h60
  text "EK-LM4F120XL_SMB.PHO" at 1702.53,3921.41 h50
  text "11. PCB THICKNESS SHALL BE 0.062\" +/- 0.007\"." at 3116,3822 h50
  text "12. WARP/TWIST SHALL NOT EXCEED .010 INCH PER INCH." at 3116,3697 h50
  text "13. FINISH SHALL BE LPI, GLOSS RED SMOBC, BOTH SIDES. BALANCE OF EXPOSED" at 3116,3572 h50
  text "COPPER SHALL BE HASL." at 3276,3452 h50
  text "14. SILKSCREEN WITH NONCONDUCTIVE WHITE EPOXY INK." at 3126,3327 h50
Layer_25:
  drawing of 189 lines, arcs and shapes, not listed
  text "300mil" at 580,2710.5 h50
  text "500mil" at -388,1924 h50
  text "1100mil" at -1084.36,1912.5 h50
  text "400mil" at -296,1816 h50
  text "700mil" at -886.68,1712.5 h50
  text "345mil" at 2128,1544 h50
  text "100mil" at -484,1308 h50
  text "2600mil" at -696,1016 h50
  text "1400mil" at -1099.73,662.5 h50
  text "200mil" at -456,364 h50
  text "500mil" at -343.64,-265.5 h50
  text "1100mil" at 513.64,-381.5 h50
  text "900mil" at 420.45,-513.5 h50
  text "1600mil" at 854.55,-629.5 h50
  text "1800mil" at 853.41,-765.5 h50
  text "2000mil" at 843.18,-873.5 h50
